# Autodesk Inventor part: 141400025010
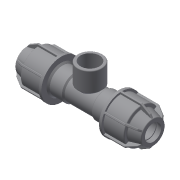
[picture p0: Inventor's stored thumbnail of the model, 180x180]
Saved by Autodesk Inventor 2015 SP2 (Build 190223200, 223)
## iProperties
Created: 2017-08
Part Number: 141400025010
Material: Generic
Description: PLASSON L.14 TEE FEMALE ADAPTOR (SILVER) 25 x 1" x 25
Document SubType Name: Modeling
Designer: KIM
Density: 1 g/cm^3
Appearance: Default
Author: KIM
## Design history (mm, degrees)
derived "141400.ipt"
feature "Solid1::141400.ipt"
feature "Solid2::141400.ipt"
tag "TaggingFeature1"
body "Solid1"
other parameters: "d1" = 25, "d2" = 48, "d4" = 15 deg, "d5" = 31.68, "d6" = 10.4544, "d16" = 25.5, "d17" = 2.4, "d24" = 2.4, "d25" = 45, "d26" = 37.5, "d27" = 2.4, "d28" = 135 deg, "d29" = 1.44, "d31" = 1.25, "d46" = 150 deg, "d49" = 2.5, "d50" = 0, "d58" = 0.75, "d61" = 360 deg, "d63" = 22.5, "d64" = 61.5, "d80" = 36, "d81" = 2, "d84" = 2.4, "d95" = 30.291, "d96" = 39.3783, "d97" = 21, "d98" = 22.5, "d99" = 27.56481, "d100" = 135 deg, "d108" = 1.25, "d111" = 0, "d_" = 25, "G_" = 30.291, "H_" = 123, "l_" = 48, "l_2" = 21
